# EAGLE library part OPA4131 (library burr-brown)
General Purpose FET-Input Operational Amplifiers
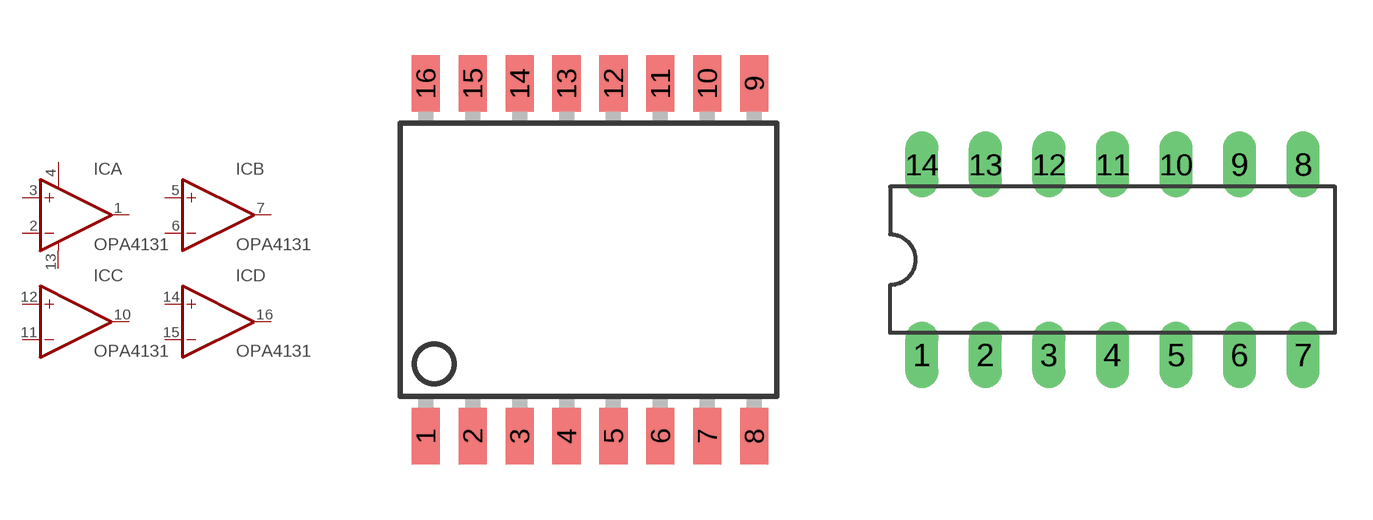
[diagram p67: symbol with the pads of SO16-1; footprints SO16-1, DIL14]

Designator prefix IC; gates A=OP-AMP+- B=OP-AMP C=OP-AMP D=OP-AMP

## OPA4131U (MF: TEXAS INSTRUMENTS; MPN: OPA4131UA; OC_FARNELL: 1459611; OC_NEWARK: 75C4950)  [SO16-1]
1  A:OUT  out
2  A:-IN  in
3  A:+IN  in
4  A:V+  pwr
5  B:+IN  in
6  B:-IN  in
7  B:OUT  out
10  C:OUT  out
11  C:-IN  in
12  C:+IN  in
13  A:V-  pwr
14  D:+IN  in
15  D:-IN  in
16  D:OUT  out

## OPA4131P (MF: TEXAS INSTRUMENTS; MPN: OPA4131PA; OC_FARNELL: 1509638; OC_NEWARK: 80K6027)  [DIL14]
1  A:OUT  out
2  A:-IN  in
3  A:+IN  in
4  A:V+  pwr
5  B:+IN  in
6  B:-IN  in
7  B:OUT  out
8  C:OUT  out
9  C:-IN  in
10  C:+IN  in
11  A:V-  pwr
12  D:+IN  in
13  D:-IN  in
14  D:OUT  out

## OPA4131N (MF: TEXAS INSTRUMENTS; MPN: OPA4131NA; OC_FARNELL: 1564896; OC_NEWARK: 80K6025)  [SO14]
Pads as for DIL14

## Footprint SO16-1 (pad centres in mm)
Small Outline Package
smd 0.762 x 1.524: 1 -4.445,-4.775; 2 -3.175,-4.775; 3 -1.905,-4.775; 4 -0.635,-4.775; 5 0.635,-4.775; 6 1.905,-4.775; 7 3.175,-4.775; 8 4.445,-4.775; 9 4.445,4.775; 10 3.175,4.775; 11 1.905,4.775; 12 0.635,4.775; 13 -0.635,4.775; 14 -1.905,4.775; 15 -3.175,4.775; 16 -4.445,4.775

## Footprint DIL14 (pad centres in mm)
Dual In Line Package
drill 0.813 long: 1 -7.62,-3.81; 2 -5.08,-3.81; 3 -2.54,-3.81; 4 0,-3.81; 5 2.54,-3.81; 6 5.08,-3.81; 7 7.62,-3.81; 8 7.62,3.81; 9 5.08,3.81; 10 2.54,3.81; 11 0,3.81; 12 -2.54,3.81; 13 -5.08,3.81; 14 -7.62,3.81

## Footprint SO14 (pad centres in mm)
Small Outline Package
smd 0.61 x 2.21: 1 -3.81,-2.603; 2 -2.54,-2.603; 3 -1.27,-2.603; 4 0,-2.603; 5 1.27,-2.603; 6 2.54,-2.603; 7 3.81,-2.603; 8 3.81,2.603; 9 2.54,2.603; 10 1.27,2.603; 11 0,2.603; 12 -1.27,2.603; 13 -2.54,2.603; 14 -3.81,2.603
